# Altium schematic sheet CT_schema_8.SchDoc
size 372 x 245 mm
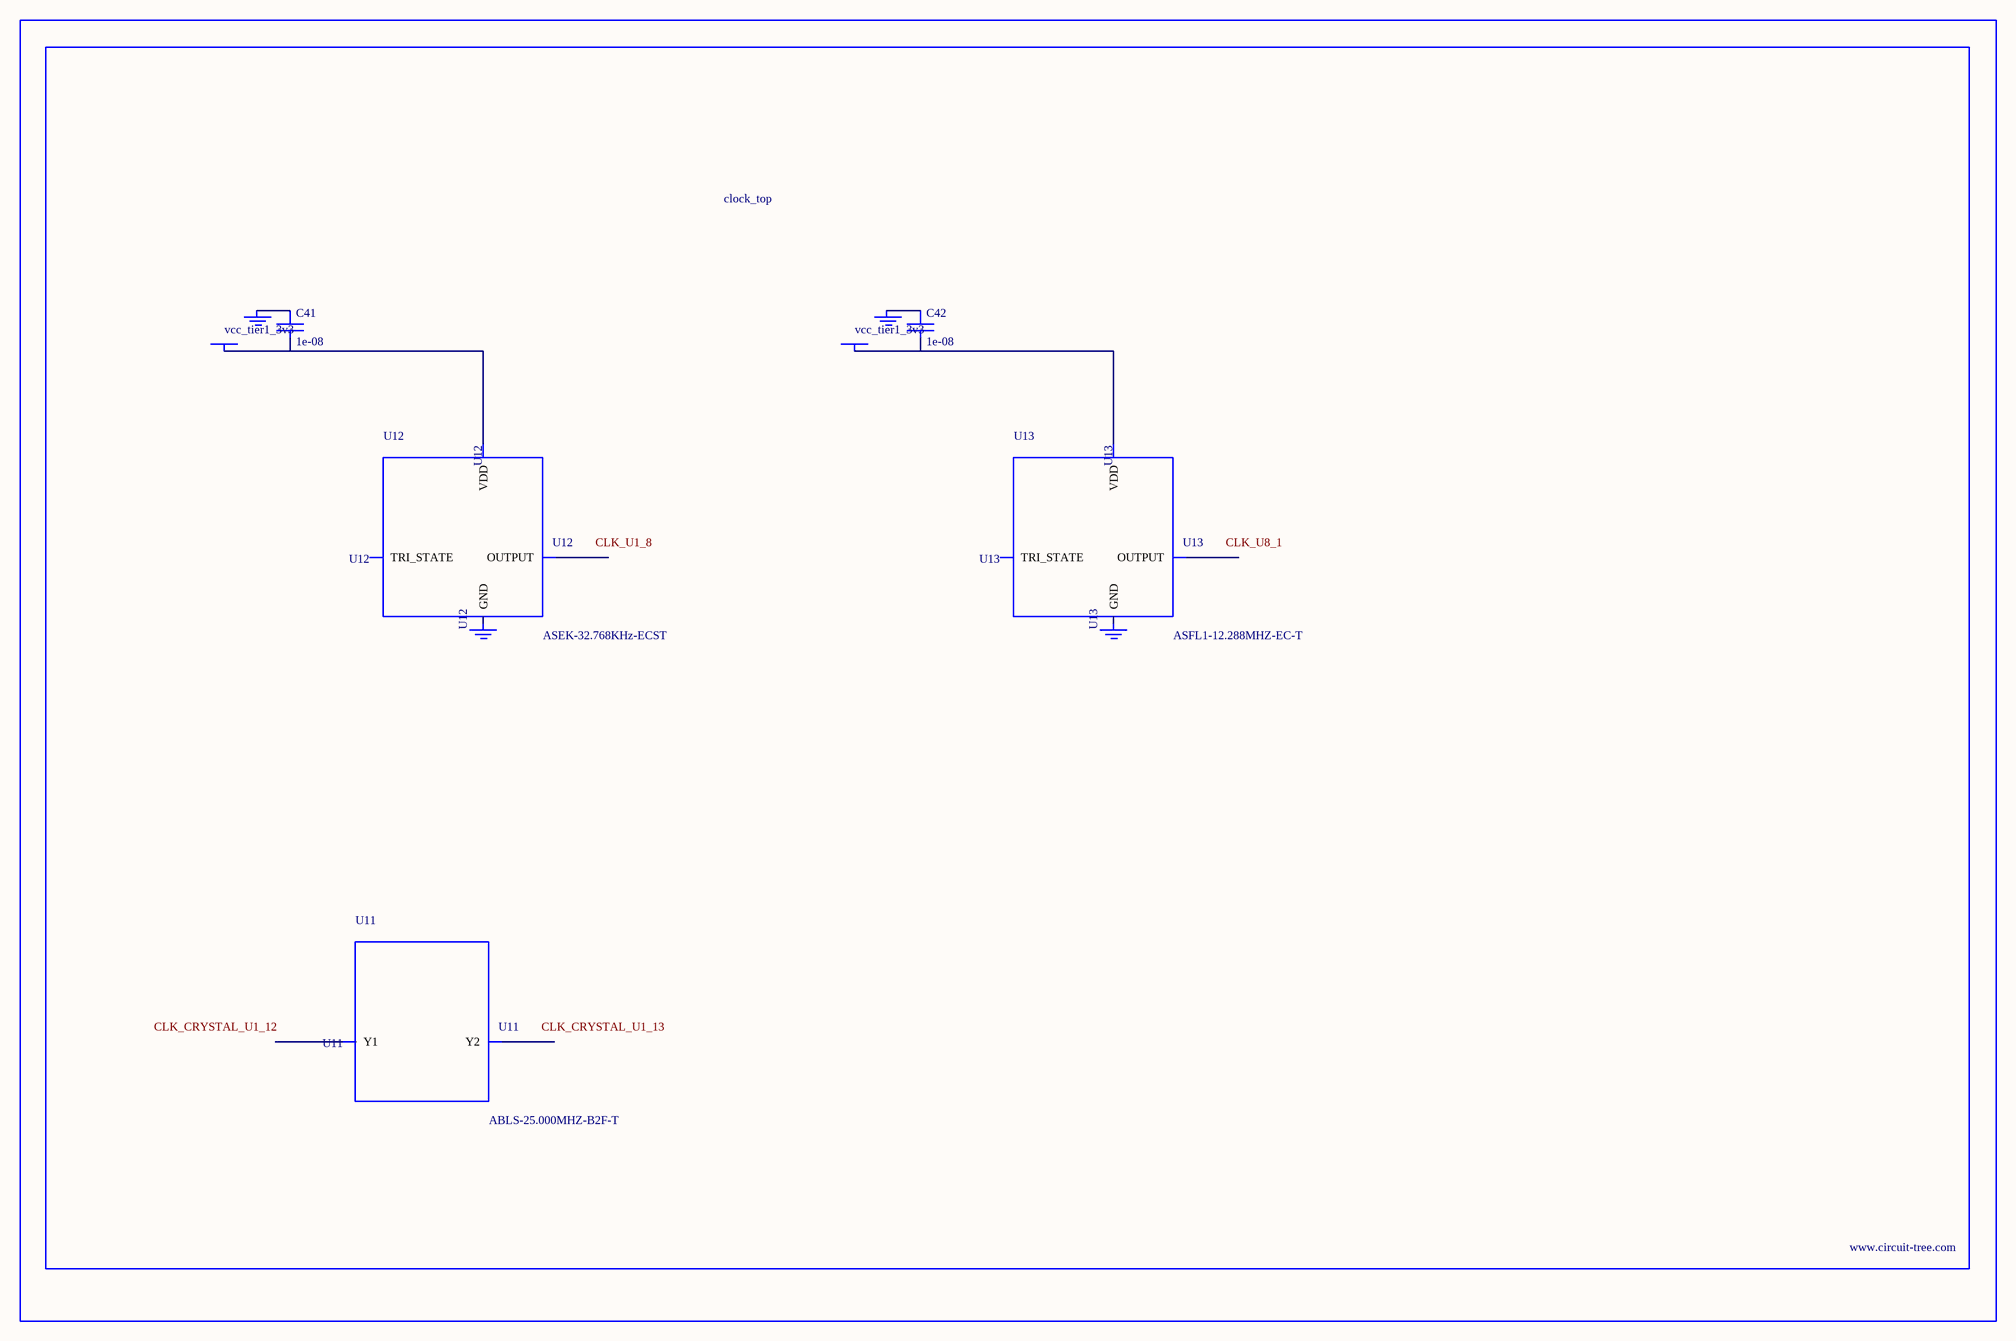
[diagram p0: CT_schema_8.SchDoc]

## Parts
BORDER7  (no value)
C41  1e-08  [C0402]
C42  1e-08  [C0402]
GND_INSTANCE_7_0  (no value)
GND_INSTANCE_7_1  (no value)
GND_INSTANCE_7_2  (no value)
GND_INSTANCE_7_3  (no value)
POWER_INSTANCE_7_0  vcc_tier1_3v3
POWER_INSTANCE_7_1  vcc_tier1_3v3
U11  ABLS-25.000MHZ-B2F-T  [ABLS-25.000MHZ-B2F-T]
U12  ASEK-32.768KHz-ECST  [ASEK]
U13  ASFL1-12.288MHZ-EC-T  [ASFL1]

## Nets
NetC41_1: C41.1 GND_INSTANCE_7_0.0(GND)
NetC41_2: C41.2 POWER_INSTANCE_7_0.0(PWR) U12.4(VDD)
NetC42_1: C42.1 GND_INSTANCE_7_2.0(GND)
NetC42_2: C42.2 POWER_INSTANCE_7_1.0(PWR) U13.4(VDD)

Not connected (* = marked no-connect by the designer): GND_INSTANCE_7_1 0(GND); GND_INSTANCE_7_3 0(GND); U11 1(Y1) 2(Y2); U12 1(TRI_STATE) 2(GND) 3(OUTPUT); U13 1(TRI_STATE) 2(GND) 3(OUTPUT)

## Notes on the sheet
- Labels drawn without touching a wire or pin: CLK_CRYSTAL_U1_12, CLK_CRYSTAL_U1_13, CLK_U1_8, CLK_U8_1

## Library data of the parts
BORDER7 = BORDER_PAGE7
C41 C42 = C0402C103K3RAC
GND_INSTANCE_7_0-GND_INSTANCE_7_3 = GND
POWER_INSTANCE_7_0 POWER_INSTANCE_7_1 = PWR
